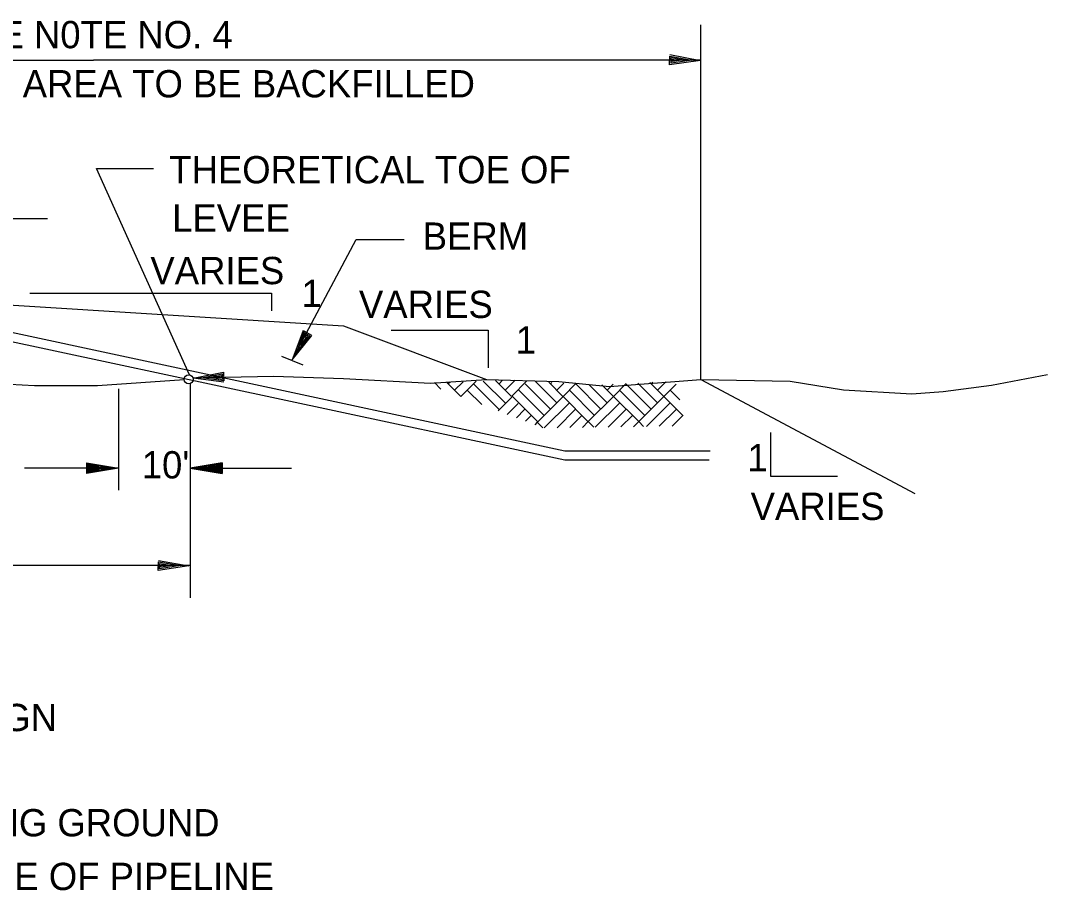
# Model space of a CAD drawing. Extents: x 2127959 to 2137375, y 2146193 to 2153470.
# Drawn here: x 2131850 to 2133089, y 2149874 to 2150923 of the extents above; entities that cross this region are included whole.
import ezdxf

# ---------------------------------------------------------------- set-up
doc = ezdxf.new("R2010")
doc.units = 0
for name, color, linetype in [('Level 1', 7, 'Continuous'), ('Level 3', 7, 'Continuous'), ('Level 5', 7, 'Continuous'), ('Level 50', 7, 'Continuous')]:
    doc.layers.add(name, color=color, linetype=linetype)

msp = doc.modelspace()

# ---------------------------------------------------------------- linework, layer by layer
at = {"layer": 'Level 1'}
for p, q in [((2132053.86, 2150495.333), (2131941.715, 2150744.479)), ((2131941.715, 2150744.479), (2132010.61, 2150744.479)), ((2132178.069, 2150513.667), (2132255.258, 2150658.712)), ((2132255.258, 2150658.712), (2132312.905, 2150658.712)), ((2131695.401, 2150588.702), (2132239.818, 2150554.673)), ((2132239.818, 2150554.673), (2132412.219, 2150490.024)), ((2132165.199, 2150518.196), (2132190.629, 2150507.689)), ((2132670.821, 2150490.024), (2132929.423, 2150352.518))]:
    msp.add_line(p, q, dxfattribs=at)
at = {"layer": 'Level 3'}
for p, q in [((2132670.821, 2150490.024), (2132670.821, 2150917.565)), ((2131205.402, 2150875.068), (2131938.111, 2150875.068)), ((2132670.821, 2150875.068), (2131938.111, 2150875.068)), ((2131315.548, 2150683.978), (2131882.694, 2150683.978)), ((2131248.552, 2150673.424), (2132506.745, 2150403.823)), ((2131551.79, 2150597.432), (2132506.745, 2150392.79)), ((2131861.286, 2150594.086), (2132152.856, 2150594.086)), ((2132152.856, 2150594.086), (2132152.856, 2150572.64)), ((2132297.439, 2150549.521), (2132414.439, 2150549.521)), ((2132414.439, 2150549.521), (2132414.439, 2150504.049)), ((2131867.045, 2150482.766), (2131942.952, 2150482.766)), ((2131968.471, 2150478.437), (2131968.471, 2150356.535)), ((2132054.671, 2150484.868), (2132054.671, 2150226.611)), ((2132755.347, 2150372.964), (2132755.347, 2150425.977)), ((2132506.745, 2150403.823), (2132682.126, 2150403.823)), ((2131929.712, 2150389.445), (2131929.712, 2150376.517)), ((2131929.712, 2150389.445), (2131968.471, 2150382.98)), ((2132093.427, 2150389.445), (2132054.671, 2150382.98)), ((2132092.618, 2150388.652), (2132061.223, 2150383.428)), ((2132092.686, 2150383.891), (2132092.618, 2150388.652)), ((2132093.427, 2150389.445), (2132093.427, 2150376.517)), ((2132506.745, 2150393.047), (2132681.043, 2150393.047)), ((2131968.471, 2150382.98), (2131854.703, 2150382.98)), ((2131968.471, 2150382.98), (2131929.712, 2150382.98)), ((2131968.471, 2150382.98), (2131929.712, 2150376.517)), ((2131930.282, 2150377.31), (2131962.677, 2150382.495)), ((2131930.44, 2150382.343), (2131930.282, 2150377.31)), ((2131930.475, 2150388.308), (2131930.422, 2150383.531)), ((2131930.422, 2150383.531), (2131962.729, 2150383.394)), ((2131962.677, 2150382.495), (2131931.229, 2150382.363)), ((2131931.229, 2150382.363), (2131931.229, 2150378.222)), ((2131931.229, 2150378.222), (2131955.264, 2150381.825)), ((2131931.301, 2150388.359), (2131931.279, 2150384.119)), ((2131931.279, 2150384.119), (2131955.487, 2150383.946)), ((2131962.729, 2150383.394), (2131931.301, 2150388.359)), ((2131955.264, 2150381.825), (2131932.041, 2150381.498)), ((2131932.041, 2150381.498), (2131932.127, 2150379.099)), ((2131932.127, 2150379.099), (2131944.796, 2150380.807)), ((2131955.487, 2150383.946), (2131932.144, 2150387.407)), ((2131932.144, 2150387.407), (2131932.144, 2150385.032)), ((2131932.144, 2150385.032), (2131944.625, 2150384.824)), ((2131944.796, 2150380.807), (2131933.026, 2150380.873)), ((2131933.026, 2150380.873), (2131933.041, 2150379.912)), ((2131933.041, 2150379.912), (2131936.625, 2150380.207)), ((2131944.625, 2150384.824), (2131933.075, 2150386.671)), ((2131933.075, 2150386.671), (2131933.094, 2150385.704)), ((2131933.094, 2150385.704), (2131936.766, 2150385.598)), ((2132054.671, 2150382.98), (2132177.147, 2150382.98)), ((2132054.671, 2150382.98), (2132093.427, 2150382.98)), ((2132054.671, 2150382.98), (2132093.427, 2150376.517)), ((2132061.223, 2150383.428), (2132091.995, 2150383.787)), ((2132092.79, 2150377.393), (2132061.325, 2150382.375)), ((2132061.325, 2150382.375), (2132091.943, 2150382.375)), ((2132091.943, 2150387.84), (2132067.446, 2150383.912)), ((2132067.446, 2150383.912), (2132091.083, 2150384.55)), ((2132092.045, 2150378.185), (2132067.6, 2150381.894)), ((2132067.6, 2150381.894), (2132091.185, 2150381.652)), ((2132091.016, 2150386.892), (2132076.703, 2150384.737)), ((2132076.703, 2150384.737), (2132090.289, 2150384.978)), ((2132091.151, 2150379.085), (2132076.895, 2150381.152)), ((2132076.895, 2150381.152), (2132090.393, 2150380.929)), ((2132090.564, 2150379.79), (2132086.239, 2150380.358)), ((2132090.357, 2150386.15), (2132086.253, 2150385.531)), ((2132090.289, 2150384.978), (2132090.357, 2150386.15)), ((2132090.393, 2150380.929), (2132090.564, 2150379.79)), ((2132091.083, 2150384.55), (2132091.016, 2150386.892)), ((2132091.185, 2150381.652), (2132091.151, 2150379.085)), ((2132091.995, 2150383.787), (2132091.943, 2150387.84)), ((2132091.943, 2150382.375), (2132092.045, 2150378.185)), ((2132092.72, 2150382.363), (2132092.79, 2150377.393)), ((2132836.085, 2150372.964), (2132755.347, 2150372.964)), ((2132054.671, 2150265.559), (2131205.781, 2150265.559))]:
    msp.add_line(p, q, dxfattribs=at)
msp.add_circle((2132053.051, 2150490.007), 5.379, dxfattribs=at)
at = {"layer": 'Level 5'}
for p, q in [((2131942.952, 2150482.766), (2132047.673, 2150489.78)), ((2132058.065, 2150491.971), (2132155.286, 2150493.938)), ((2132155.286, 2150493.938), (2132239.916, 2150491.126)), ((2132239.916, 2150491.126), (2132344.842, 2150485.267)), ((2132344.842, 2150485.267), (2132412.219, 2150490.024)), ((2132381.494, 2150469.318), (2132399.904, 2150487.733)), ((2132408.545, 2150488.028), (2132434.867, 2150461.7)), ((2132412.219, 2150490.024), (2132499.468, 2150487.625)), ((2132442.486, 2150469.318), (2132423.301, 2150488.507)), ((2132431.476, 2150488.784), (2132427.868, 2150485.176)), ((2132446.87, 2150488.954), (2132435.49, 2150477.558)), ((2132443.112, 2150469.938), (2132461.244, 2150488.076)), ((2132560.606, 2150481.319), (2132670.821, 2150490.024)), ((2132670.821, 2150490.024), (2132778.743, 2150487.746)), ((2132778.743, 2150487.746), (2132843.118, 2150477.49)), ((2133021.829, 2150483.127), (2133089.29, 2150495.749)), ((2131781.825, 2150487.367), (2131867.045, 2150482.766)), ((2132349.496, 2150486.077), (2132357.459, 2150478.112)), ((2132381.494, 2150469.318), (2132364.254, 2150486.561)), ((2132368.392, 2150486.697), (2132366.253, 2150484.556)), ((2132384.131, 2150487.214), (2132373.872, 2150476.939)), ((2132406.562, 2150459.51), (2132389.115, 2150476.939)), ((2132396.787, 2150484.556), (2132427.267, 2150454.079)), ((2132481.846, 2150446.457), (2132451.335, 2150476.956)), ((2132489.435, 2150454.096), (2132458.956, 2150484.578)), ((2132471.329, 2150487.472), (2132497.091, 2150461.713)), ((2132487.52, 2150486.491), (2132504.675, 2150469.335)), ((2132491.178, 2150486.269), (2132489.488, 2150484.578)), ((2132505.537, 2150485.405), (2132497.091, 2150476.956)), ((2132499.468, 2150487.625), (2132560.606, 2150481.319)), ((2132504.728, 2150469.335), (2132519.916, 2150484.545)), ((2132542.689, 2150446.615), (2132512.346, 2150476.956)), ((2132550.308, 2150454.233), (2132520.003, 2150484.524)), ((2132536.259, 2150483.558), (2132557.946, 2150461.87)), ((2132551.467, 2150483.543), (2132565.671, 2150469.335)), ((2132565.309, 2150484.176), (2132558.067, 2150476.939)), ((2132565.532, 2150469.459), (2132580.98, 2150484.885)), ((2132603.497, 2150446.457), (2132572.996, 2150476.956)), ((2132580.652, 2150484.556), (2132611.133, 2150454.096)), ((2132594.912, 2150485.524), (2132618.735, 2150461.7)), ((2132626.376, 2150469.335), (2132609.497, 2150486.195)), ((2132612.927, 2150486.353), (2132611.133, 2150484.556)), ((2132628.876, 2150487.094), (2132618.735, 2150476.956)), ((2132626.376, 2150469.335), (2132641.321, 2150484.284)), ((2132645.476, 2150465.473), (2132633.993, 2150476.956)), ((2132843.118, 2150477.49), (2132925.785, 2150472.766)), ((2132963.388, 2150475.232), (2133021.829, 2150483.127)), ((2132443.112, 2150468.716), (2132426.387, 2150451.991)), ((2132443.712, 2150469.335), (2132474.196, 2150438.856)), ((2132504.728, 2150469.335), (2132474.245, 2150438.856)), ((2132504.728, 2150469.335), (2132535.19, 2150438.856)), ((2132535.068, 2150438.993), (2132565.532, 2150469.459)), ((2132596.014, 2150438.993), (2132565.532, 2150469.459)), ((2132626.376, 2150469.335), (2132595.891, 2150438.856)), ((2132649.787, 2150445.976), (2132626.425, 2150469.335)), ((2132925.785, 2150472.766), (2132963.388, 2150475.232)), ((2132437.437, 2150447.802), (2132450.728, 2150461.094)), ((2132448.486, 2150443.63), (2132458.349, 2150453.476)), ((2132482.022, 2150431.389), (2132512.346, 2150461.713)), ((2132497.469, 2150431.615), (2132519.949, 2150454.096)), ((2132543.549, 2150432.27), (2132573.171, 2150461.887)), ((2132580.774, 2150454.214), (2132559.033, 2150432.492)), ((2132605.443, 2150433.148), (2132633.993, 2150461.7)), ((2132620.873, 2150433.373), (2132641.613, 2150454.096)), ((2132465.989, 2150445.837), (2132459.558, 2150439.424)), ((2132473.591, 2150438.232), (2132470.59, 2150435.252)), ((2132473.591, 2150438.197), (2132480.158, 2150431.615)), ((2132527.587, 2150446.457), (2132512.968, 2150431.838)), ((2132528.121, 2150432.046), (2132535.068, 2150438.993)), ((2132541.792, 2150432.234), (2132535.068, 2150438.993)), ((2132588.411, 2150446.628), (2132574.479, 2150432.7)), ((2132589.963, 2150432.923), (2132596.014, 2150438.993)), ((2132596.014, 2150438.993), (2132601.909, 2150433.097)), ((2132649.253, 2150446.457), (2132636.376, 2150433.578))]:
    msp.add_line(p, q, dxfattribs=at)
at = {"layer": 'Level 50'}
for p, q in [((2132660.213, 2150875.011), (2132660.213, 2150875.011)), ((2132670.497, 2150874.753), (2132670.497, 2150874.753)), ((2132178.069, 2150513.667), (2132178.069, 2150513.667)), ((2132183.13, 2150522.609), (2132183.13, 2150522.609)), ((2132058.314, 2150491.565), (2132058.314, 2150491.565)), ((2132068.59, 2150491.846), (2132068.59, 2150491.846)), ((2132043.047, 2150265.331), (2132043.047, 2150265.331)), ((2132053.333, 2150265.25), (2132053.333, 2150265.25))]:
    msp.add_line(p, q, dxfattribs=at)
for points in [[(2132633.673, 2150881.791), (2132670.497, 2150874.753), (2132633.386, 2150869.529), (2132633.643, 2150880.007), (2132660.213, 2150875.011), (2132635.021, 2150871.47), (2132635.175, 2150878.2), (2132650.336, 2150875.258), (2132636.651, 2150873.408), (2132636.712, 2150876.174), (2132640.053, 2150875.504)], [(2132190.999, 2150548.842), (2132178.069, 2150513.667), (2132201.66, 2150542.787), (2132192.549, 2150547.966), (2132183.13, 2150522.609), (2132199.151, 2150542.381), (2132193.31, 2150545.72), (2132188.015, 2150531.207), (2132196.649, 2150541.981), (2132194.234, 2150543.35), (2132193.092, 2150540.147)], [(2132095.451, 2150486.463), (2132058.314, 2150491.565), (2132095.097, 2150498.722), (2132095.389, 2150488.248), (2132068.59, 2150491.846), (2132093.565, 2150496.698), (2132093.761, 2150489.972), (2132078.468, 2150492.114), (2132092.041, 2150494.679), (2132092.122, 2150491.914), (2132088.751, 2150492.411)], [(2132016.393, 2150271.647), (2132053.333, 2150265.25), (2132016.318, 2150259.383), (2132016.39, 2150269.862), (2132043.047, 2150265.331), (2132017.924, 2150261.35), (2132017.957, 2150268.08), (2132033.167, 2150265.402), (2132019.515, 2150263.319), (2132019.529, 2150266.083), (2132022.882, 2150265.47)]]:
    msp.add_lwpolyline(points, dxfattribs=at)

# ---------------------------------------------------------------- texts
at = {"layer": 'Level 1'}
for s, p in [('SEE N0TE NO. 4 ', (2131765.911, 2150889.419)), ('EXCAVATION IN THIS AREA TO BE BACKFILLED ', (2131387.81, 2150830.14)), ('THEORETICAL TOE OF ', (2132029.537, 2150726.463)), ('LEVEE', (2132033.042, 2150668.128)), ('BERM', (2132335.453, 2150646.317)), ('VARIES', (2132006.775, 2150604.828)), ('1', (2132189.162, 2150577.155)), ('VARIES', (2132258.453, 2150564.054)), ('1', (2132447.575, 2150521.039)), ("10'", (2131996.358, 2150370.493)), ('1', (2132727.142, 2150379.171)), ('VARIES', (2132731.118, 2150320.412)), ('ALL PIPELINES MUST BE PLACED ABOVE LEVEE DESIGN', (2130680.258, 2150065.69)), ('DASHED LINE INCLUDING EXTENSION BELOW EXISTING GROUND', (2130678.443, 2149938.769)), ('SURFACE IF LEVEE EMBANKMENT EXISTS AT THE TIME OF PIPELINE', (2130677.939, 2149873.989))]:
    msp.add_text(s, height=32.931, dxfattribs=at).set_placement(p)

doc.saveas('drawing.dxf')
